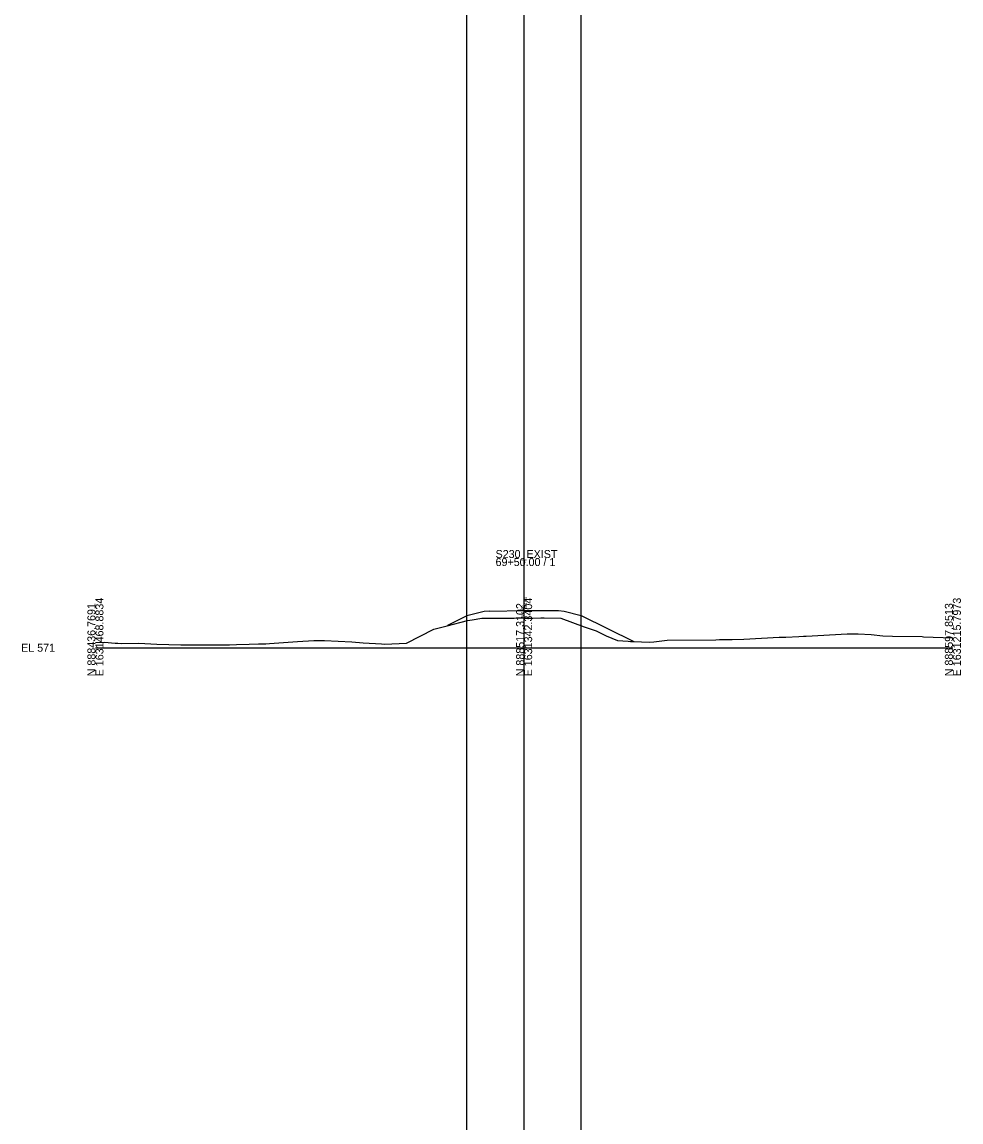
# Model space of a CAD drawing. Extents: x 1631115 to 1631443, y 885974 to 892071.
# Drawn here: x 1631114.8 to 1631443.3, y 888317.8 to 888702.5 of the extents above; entities that cross this region are included whole.
import ezdxf

# ---------------------------------------------------------------- set-up
doc = ezdxf.new("R2010")
doc.units = 0
for name, color, linetype in [('Default', 7, 'Continuous'), ('RD_GPK_XS_Cell', 7, 'Continuous'), ('RD_XS_EarthShd', 7, 'Continuous'), ('RD_XS_ExGround', 7, 'Continuous'), ('RD_XS_Pave', 7, 'Continuous'), ('RD_XS_TieSlope', 7, 'Continuous'), ('RD_XS_TX_Elev_EX', 7, 'Continuous'), ('RD_XS_TX_Elev_PR', 7, 'Continuous')]:
    doc.layers.add(name, color=color, linetype=linetype)

msp = doc.modelspace()

# ---------------------------------------------------------------- linework, layer by layer
at = {"layer": 'Default'}
for p, q in [((1631270.47, 885983.65), (1631270.47, 892068.63)), ((1631290.47, 885983.65), (1631290.47, 892068.63)), ((1631310.47, 885983.65), (1631310.47, 892068.63))]:
    msp.add_line(p, q, dxfattribs=at)
at = {"layer": 'RD_GPK_XS_Cell'}
for p, q in [((1631290.47, 888483.65), (1631290.47, 888515.02)), ((1631140.47, 888483.65), (1631290.47, 888483.65)), ((1631290.47, 888483.65), (1631440.47, 888483.65))]:
    msp.add_line(p, q, dxfattribs=at)
at = {"layer": 'RD_XS_EarthShd'}
for p, q in [((1631278.47, 888496.45), (1631276.47, 888496.29)), ((1631302.47, 888496.64), (1631304.47, 888496.48))]:
    msp.add_line(p, q, dxfattribs=at)
at = {"layer": 'RD_XS_ExGround'}
msp.add_lwpolyline([(1631140.47, 888485.45), (1631143.67, 888485.62), (1631147.33, 888485.28), (1631148.34, 888485.2), (1631149.67, 888485.18), (1631155.71, 888485.2), (1631161.97, 888484.93), (1631170.38, 888484.65), (1631171.82, 888484.66), (1631176.66, 888484.67), (1631180.4, 888484.69), (1631187.42, 888484.7), (1631189.86, 888484.79), (1631194.22, 888484.88), (1631197.47, 888484.97), (1631200.05, 888485.06), (1631201.39, 888485.15), (1631211.18, 888485.84), (1631216.9, 888486.18), (1631217.45, 888486.23), (1631220.67, 888486.17), (1631230.16, 888485.68), (1631234.11, 888485.39), (1631240.6, 888484.98), (1631241.57, 888484.92), (1631249.31, 888485.27), (1631258.89, 888490.12), (1631263.54, 888491.36), (1631270.64, 888493.14), (1631272.25, 888493.42), (1631275.67, 888494.01), (1631278.26, 888493.98), (1631281.06, 888493.96), (1631286.49, 888494.04), (1631287.02, 888494.05), (1631288.58, 888494.06), (1631290.47, 888494.05), (1631293.46, 888494.04), (1631296.27, 888494.1), (1631297.53, 888494.11), (1631303.32, 888494.05), (1631311.47, 888490.92), (1631315.66, 888489.52), (1631319.16, 888487.85), (1631323.13, 888486.14), (1631326.9, 888485.89), (1631327.64, 888485.87), (1631328.72, 888485.81), (1631334.31, 888485.58), (1631335.86, 888485.7), (1631340.5, 888486.28), (1631357.54, 888486.46), (1631358.85, 888486.48), (1631360.02, 888486.5), (1631363.29, 888486.54), (1631367.3, 888486.68), (1631379.67, 888487.32), (1631381.48, 888487.38), (1631382, 888487.4), (1631386.54, 888487.59), (1631388.16, 888487.65), (1631389.16, 888487.69), (1631403.45, 888488.5), (1631407.3, 888488.57), (1631411.92, 888488.26), (1631415.92, 888487.76), (1631419.4, 888487.7), (1631429.69, 888487.53), (1631430.14, 888487.52), (1631440.47, 888487.09)], dxfattribs=at)
at = {"layer": 'RD_XS_Pave'}
for p, q in [((1631278.47, 888496.45), (1631290.47, 888496.69)), ((1631290.47, 888496.69), (1631302.47, 888496.64))]:
    msp.add_line(p, q, dxfattribs=at)
at = {"layer": 'RD_XS_TieSlope'}
for p, q in [((1631276.47, 888496.29), (1631270.47, 888494.79)), ((1631304.47, 888496.48), (1631310.47, 888494.98)), ((1631270.47, 888494.79), (1631263.67, 888491.39)), ((1631310.47, 888494.98), (1631328.81, 888485.81))]:
    msp.add_line(p, q, dxfattribs=at)

# ---------------------------------------------------------------- texts
at = {"layer": 'RD_GPK_XS_Cell'}
for s, p in [('S230_EXIST', (1631280.47, 888515.02)), ('69+50.00 / 1', (1631280.47, 888512.22)), ('EL 571', (1631114.47, 888482.25))]:
    msp.add_text(s, height=2.8, dxfattribs=at).set_placement(p)
for s, p in [('E 1631468.8834', (1631143.27, 888473.65)), ('E 1631342.3404', (1631293.27, 888473.65)), ('E 1631215.7973', (1631443.27, 888473.65)), ('N 888436.7691', (1631140.47, 888473.65)), ('N 888517.3102', (1631290.47, 888473.65)), ('N 888597.8513', (1631440.47, 888473.65))]:
    msp.add_text(s, height=2.8, rotation=90, dxfattribs=at).set_placement(p)
at = {"layer": 'RD_XS_TX_Elev_EX'}
msp.add_text('581.40', height=1, rotation=90, dxfattribs=at).set_placement((1631290.37, 888494.15))
at = {"layer": 'RD_XS_TX_Elev_PR'}
msp.add_text(' 584.04', height=1, rotation=90, dxfattribs=at).set_placement((1631291.47, 888496.69))

doc.saveas('drawing.dxf')
